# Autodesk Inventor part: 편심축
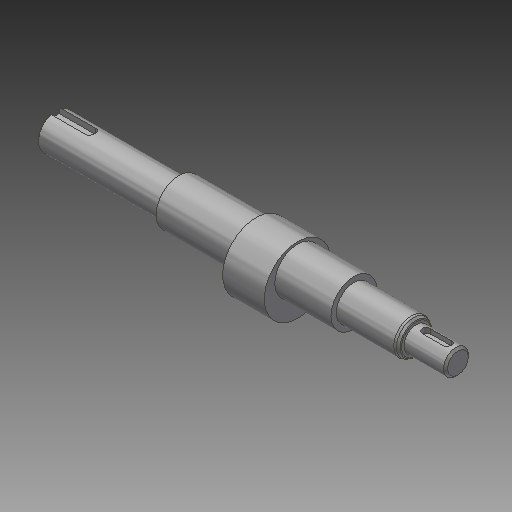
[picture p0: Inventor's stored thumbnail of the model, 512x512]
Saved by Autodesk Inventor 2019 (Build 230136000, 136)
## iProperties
Created: 2016-05
Part Number: 편심축
Document SubType Name: Modeling
Designer: mduedu
Density: 7.86 g/cm^3
Material: 강철, 연강
Appearance: 강철
Author: mduedu
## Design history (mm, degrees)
sketch "스케치1"
  geometry: L1 (-37, 11)-(-37, 8.5); L2 (47, 11)-(47, 8.5); L3 (-97, 0)-(97, 0); L4 (-37, 11)-(47, 11); L5 (47, 11)-(47, 8.5); L6 (-37, 11)-(-37, 8.5); L7 (-37, 8.5)-(-97, 8.5); L8 (-97, 8.5)-(-97, 0); L9 (47, 8.5)-(77, 8.5); L10 (97, 6)-(97, 0); L11 (77, 8.5)-(77, 6); L12 (77, 6)-(97, 6); 1 further point
  constraints: 24 end point, 9 perpendicular, 2 midpoint, 1 collinear, 1 horizontal
  dimensions: "d0" = 22 diameter of L4 L3; "d1" = 17 diameter of L7 L3; "d2" = 60 distance between parallel lines of L8 L1; "d3" = 50 distance between parallel lines of L10 L2; "d4" = 12 diameter of L12 L3; "d5" = 20 distance between parallel lines of L10 L11; "d29" = 84 distance of L1.start L2.start
revolve "회전1" stored, may be unused: angle "d6" = 90 deg
node "작업 평면7"
node "작업 평면9"
sketch "스케치2"
  geometry: C1 r 11 at (0, 0); C2 r 16 at (0, -4); C3 r 11 at (0, 0); 2 further points
  constraints: 3 centre point, 2 coincident, 1 concentric, 1 vertical alignment
  dimensions: "d9" = 4 distance of point (0, 0) C2.centre; "d10" = 32 diameter of C2
extrude "돌출1" join sketch "스케치2" stored distance "d11" = 20; taper "d12" = 0 deg
chamfer "모따기2" distance "d32" = 1; stored, may be unused: second distance "d33" = 2, angle "d34" = 45 deg
node "작업 평면4"
sketch "스케치4"
  geometry: L1 (-5, 2)-(5, 2); L2 (5, -2)-(-5, -2); L3 (-10, -5)-(-10, 5) reference; A1 r 2 centre (5, 0) between (5, -2) and (5, 2); A2 r 2 centre (-5, 0) between (-5, 2) and (-5, -2); 2 further points
  constraints: 4 end point, 4 point on circle, 4 tangent, 2 centre point, 2 horizontal alignment, 1 midpoint, 1 parallel
  dimensions: "d20" = 4 distance between parallel lines of L2 L1; "d21" = 14 dimension on A1 A2; "d35" = 3 distance edge to line of A2 L3
extrude "돌출3" cut sketch "스케치4" distance "d23" = 2.5; taper "d24" = 0 deg
node "작업 평면5"
sketch "스케치5"
  geometry: L1 (30, 2.5)-(12.5, 2.5); L2 (12.5, -2.5)-(30, -2.5); L3 (30, 7.5)-(30, -7.5) reference; A1 r 2.5 centre (12.5, 0) between (12.5, 2.5) and (12.5, -2.5); 2 further points
  constraints: 4 end point, 2 point on circle, 2 point on line, 2 tangent, 1 centre point, 1 horizontal, 1 horizontal alignment, 1 midpoint
  dimensions: "d25" = 5 distance between parallel lines of L2 L1; "d36" = 20 dimension on A1 L3
extrude "돌출4" cut sketch "스케치5" distance "d27" = 3; taper "d28" = 0 deg
chamfer "모따기3" distance "d37" = 1.82; stored, may be unused: second distance "d38" = 2, angle "d39" = 30 deg
fillet "모깎기1" dims "d40" = 2, "d41" = 0.5
node "솔리드1"
other parameters: "d31" = -37
